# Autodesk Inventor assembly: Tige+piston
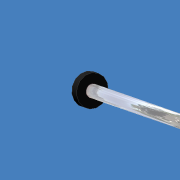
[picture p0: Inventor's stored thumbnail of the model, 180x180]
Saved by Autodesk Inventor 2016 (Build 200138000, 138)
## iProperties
Shininess: 41.0
Angle Display Precision: 2
Document Length Units: 11269
Document Angle Units: 11279
Document Time Units: 11290
Document Mass Units: 11283
Document Length Units Precision: 3
Document Angle Units Precision: 2
Created: 2002-09
Part Number: Tige+piston
Document SubType Name: Assemblage
Designer: administrateur
Mass: 137.667 g
Surface Area: 145.132 cm^2
Volume: 51.5869 cm^3
Density: 2.66863 g/cm^3
Density: 0.0
Volumn: 0.0
Area: 0.0
PropertySet Name: Model Information
Control State: 0
Master: False
Checked Out: False
Author: administrateur
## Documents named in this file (3)
- D:\Cours\1-Cours-2016-17\1Ssi\5. Statique\FAAC\Portail\Tige+piston.iam
- D:\Cours\1-Cours-2016-17\1Ssi\5. Statique\FAAC\Portail\piston.ipt
- D:\Cours\1-Cours-2016-17\1Ssi\5. Statique\FAAC\Portail\tige.ipt
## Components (2 placed, 2 different names)
1. piston:1 — Logement:1
2. tige:1 — Logement:1
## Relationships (1: Insert 1)
- Logement:1 [Insert]: piston:1 ↔ tige:1
